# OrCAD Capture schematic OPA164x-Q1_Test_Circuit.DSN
size A; title: OPA164x-Q1 SoundPlus™ JFET-Input, Automotive-Grade,; rev: 1.3; note: Datasheet: SBOS791A   EVM: N/A
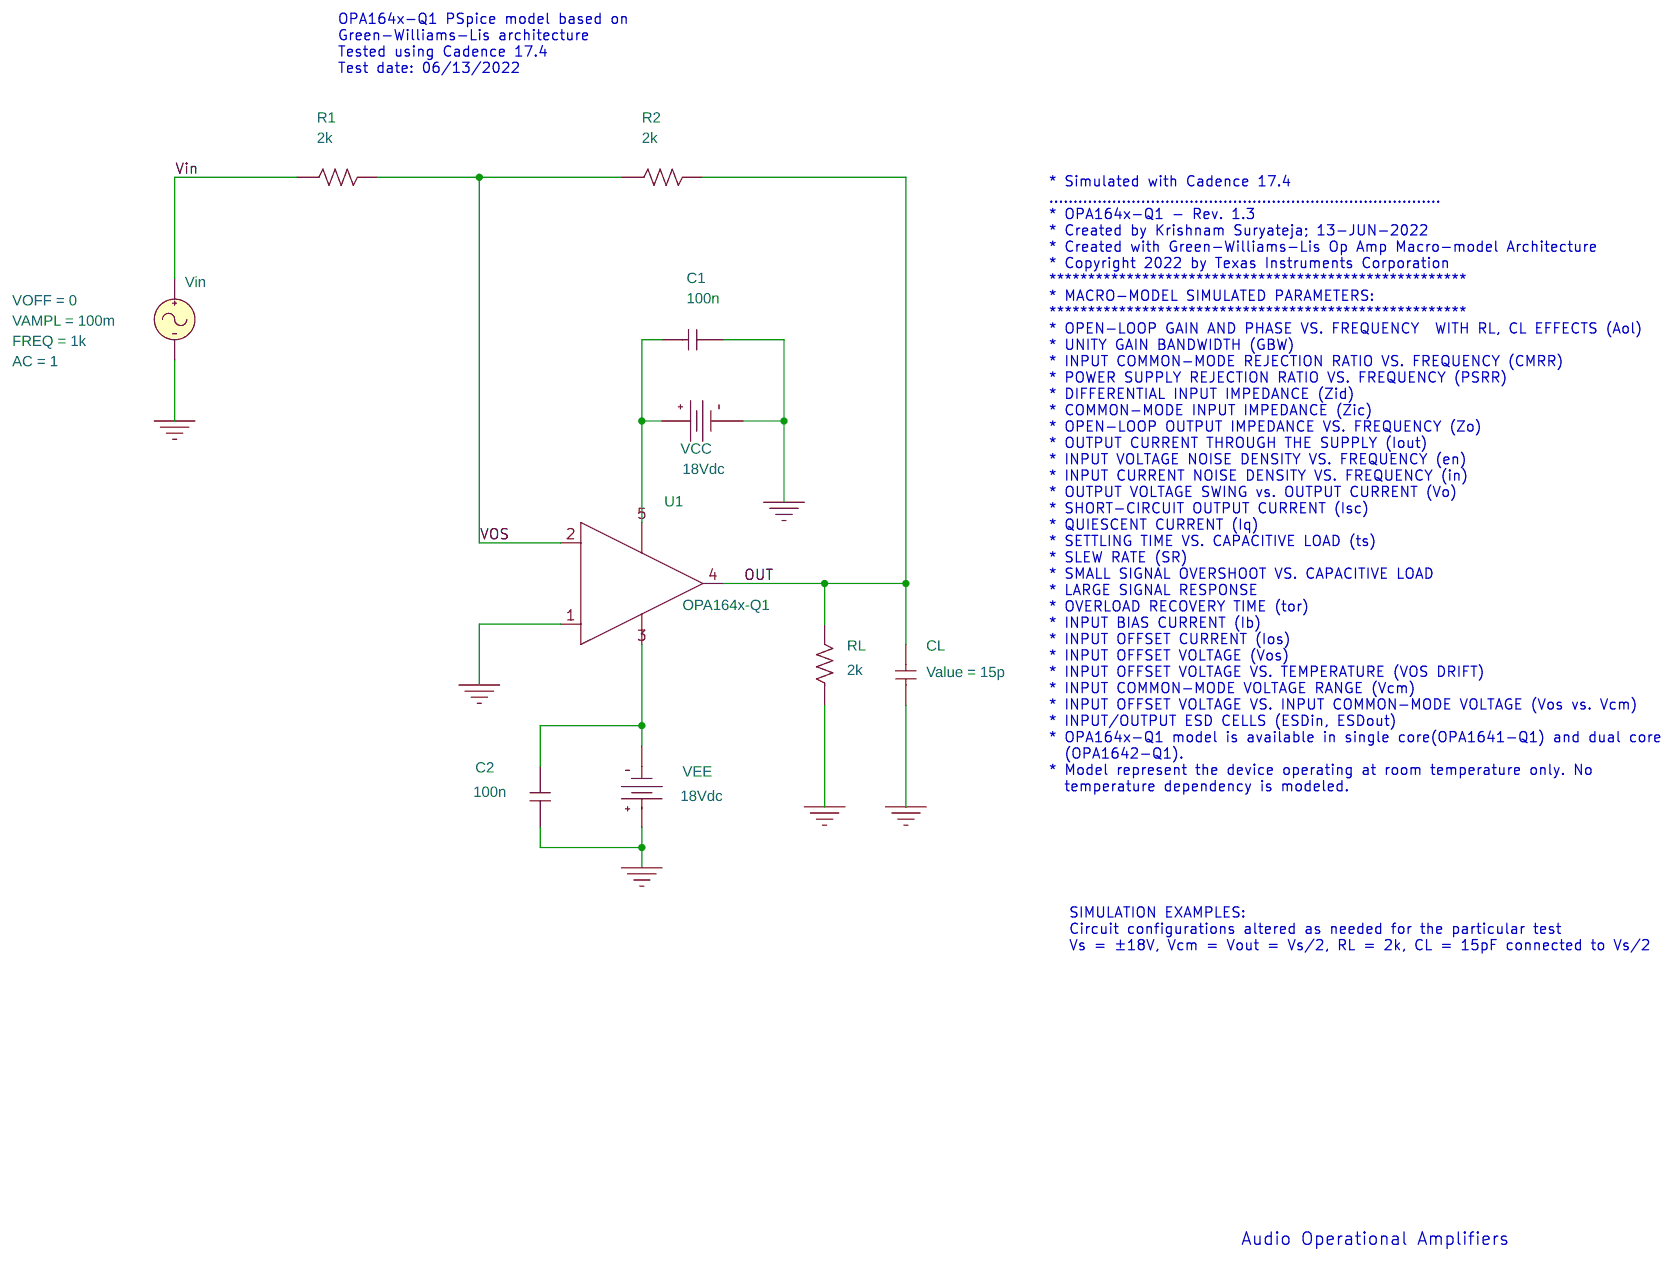
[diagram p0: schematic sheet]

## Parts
C1  100n  [cap196]
C2  100n  [cap196]
CL  15p  [cap196]
R1  2k  [AXRC05]
R2  2k  [AXRC05]
RL  2k  [AXRC05]
U1  OPA164x-Q1
VCC  VDC
VEE  VDC
Vin  VSIN

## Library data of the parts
C1 C2 CL = C
R1 R2 RL = R
U1 = OPA164x-Q1
VCC VEE = VDC: DC: 18Vdc
Vin = VSIN: AC: 1; FREQ: 1k; VAMPL: 100m; VOFF: 0

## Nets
Vin: R1.1 Vin.1(+)
0: C1.2 C2.1 CL.2 RL.1 U1.1(+) VCC.1(-) VEE.0(+) Vin.2(-)
OUT: CL.1 R2.2 RL.2 U1.4(OUT)
VOS: R1.2 R2.1 U1.2(-)
N27303: C1.1 U1.5(V+) VCC.0(+)
N27354: C2.2 U1.3(V-) VEE.1(-)

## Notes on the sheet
- OPA164x-Q1 PSpice model based on
  Green-Williams-Lis architecture
  Tested using Cadence 17.4
  Test date: 06/13/2022
- * Simulated with Cadence 17.4
  .................................................................................
  * OPA164x-Q1 - Rev. 1.3
  * Created by Krishnam Suryateja; 13-JUN-2022
  * Created with Green-Williams-Lis Op Amp Macro-model Architecture
  * Copyright 2022 by Texas Instruments Corporation
  ******************************************************
  * MACRO-MODEL SIMULATED PARAMETERS:
  ******************************************************
  * OPEN-LOOP GAIN AND PHASE VS. FREQUENCY  WITH RL, CL EFFECTS (Aol)
  * UNITY GAIN BANDWIDTH (GBW)
  * INPUT COMMON-MODE REJECTION RATIO VS. FREQUENCY (CMRR)
  * POWER SUPPLY REJECTION RATIO VS. FREQUENCY (PSRR)
  * DIFFERENTIAL INPUT IMPEDANCE (Zid)
  * COMMON-MODE INPUT IMPEDANCE (Zic)
  * OPEN-LOOP OUTPUT IMPEDANCE VS. FREQUENCY (Zo)
  * OUTPUT CURRENT THROUGH THE SUPPLY (Iout)
  * INPUT VOLTAGE NOISE DENSITY VS. FREQUENCY (en)
  * INPUT CURRENT NOISE DENSITY VS. FREQUENCY (in)
  * OUTPUT VOLTAGE SWING vs. OUTPUT CURRENT (Vo)
  * SHORT-CIRCUIT OUTPUT CURRENT (Isc)
  * QUIESCENT CURRENT (Iq)
  * SETTLING TIME VS. CAPACITIVE LOAD (ts)
  * SLEW RATE (SR)
  * SMALL SIGNAL OVERSHOOT VS. CAPACITIVE LOAD
  * LARGE SIGNAL RESPONSE
  * OVERLOAD RECOVERY TIME (tor)
  * INPUT BIAS CURRENT (Ib)
  * INPUT OFFSET CURRENT (Ios)
  * INPUT OFFSET VOLTAGE (Vos)
  * INPUT OFFSET VOLTAGE VS. TEMPERATURE (VOS DRIFT)
  * INPUT COMMON-MODE VOLTAGE RANGE (Vcm)
  * INPUT OFFSET VOLTAGE VS. INPUT COMMON-MODE VOLTAGE (Vos vs. Vcm)
  * INPUT/OUTPUT ESD CELLS (ESDin, ESDout)
  * OPA164x-Q1 model is available in single core(OPA1641-Q1) and dual core
    (OPA1642-Q1).
  * Model represent the device operating at room temperature only. No
    temperature dependency is modeled.
- SIMULATION EXAMPLES:
  Circuit configurations altered as needed for the particular test
  Vs = ±18V, Vcm = Vout = Vs/2, RL = 2k, CL = 15pF connected to Vs/2
- Audio Operational Amplifiers
